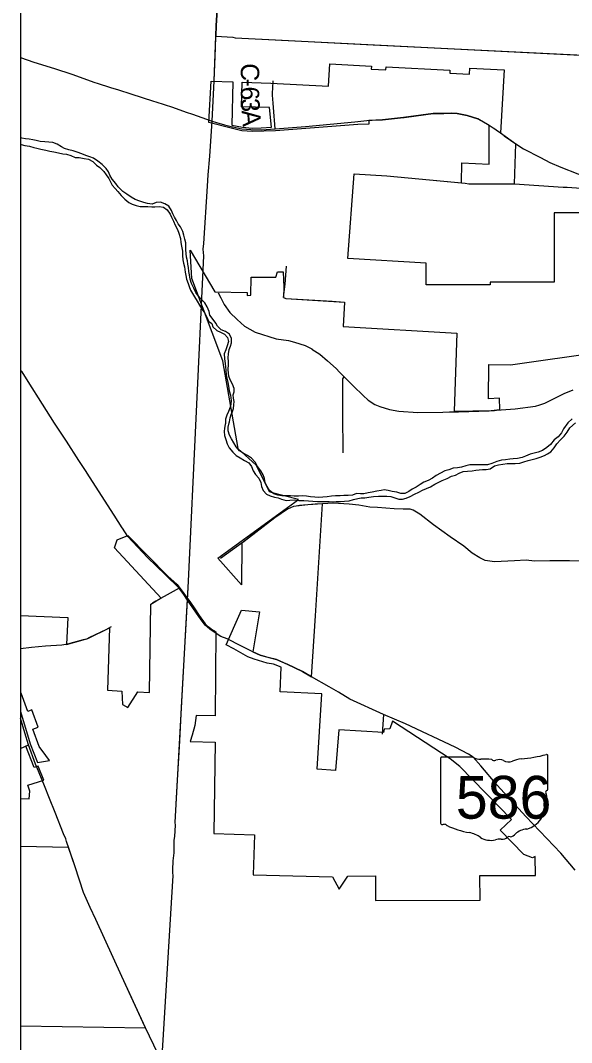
# Model space of a CAD drawing. Extents: x 41.3 to 81.6, y -19.3 to 2.7.
# Drawn here: x 43.265 to 44.697, y -1.388 to 1.27 of the extents above; entities that cross this region are included whole.
import ezdxf

# ---------------------------------------------------------------- set-up
doc = ezdxf.new("R2010")
doc.units = 0
for name, color, linetype in [('GM_X_Corporation', 7, 'Continuous'), ('GM_X_County_Road', 7, 'Continuous'), ('GM_X_County_Road_Text', 7, 'Continuous'), ('GM_X_Major_River', 7, 'Continuous'), ('GM_X_State_Route', 7, 'Continuous'), ('GM_X_State_Shield', 7, 'Continuous'), ('GM_X_Township', 7, 'Continuous'), ('GM_X_Township_Road', 7, 'Continuous'), ('SH_Data', 7, 'Continuous')]:
    doc.layers.add(name, color=color, linetype=linetype)

msp = doc.modelspace()

# ---------------------------------------------------------------- linework, layer by layer
at = {"layer": 'GM_X_Corporation'}
for points in [[(43.2645, 1.7338), (43.2645, -0.2777), (43.388, -0.2832), (43.3842, -0.3531), (43.4276, -0.3413), (43.4396, -0.3373), (43.4959, -0.3095), (43.4906, -0.4723), (43.5279, -0.4742), (43.5298, -0.5092), (43.5433, -0.5172), (43.5697, -0.4762), (43.6001, -0.4777), (43.6031, -0.248), (43.6162, -0.2404), (43.6303, -0.2329), (43.5094, -0.1021), (43.5157, -0.081), (43.5434, -0.0695), (43.6476, -0.1753), (43.6715, -0.1968), (43.7065, -0.244), (43.7181, -0.2604), (43.7293, -0.2776), (43.745, -0.2996), (43.7501, -0.3044), (43.7552, -0.3082), (43.7641, -0.3147), (43.7687, -0.3177), (43.7709, -0.3191), (43.7725, -0.3204), (43.7704, -0.5385), (43.7214, -0.5381), (43.718, -0.5638), (43.711, -0.5892), (43.7057, -0.6058), (43.771, -0.6074), (43.7675, -0.8448), (43.8728, -0.8478), (43.8698, -0.9517), (44.0759, -0.9576), (44.0935, -0.989), (44.1152, -0.9554), (44.1872, -0.9551), (44.1874, -1.0191), (44.4594, -1.0182), (44.4592, -0.9542), (44.6032, -0.9536), (44.603, -0.9047), (44.5956, -0.9077), (44.5732, -0.8991), (44.5119, -0.8359), (44.5407, -0.8081), (44.4071, -0.6702), (44.3818, -0.6505), (44.2316, -0.5529), (44.2247, -0.5725), (44.2097, -0.5731), (44.2085, -0.5823), (44.0926, -0.5748), (44.0834, -0.6809), (44.0359, -0.6774), (44.0482, -0.4814), (43.9398, -0.4759), (43.9419, -0.4122), (43.922, -0.4044), (43.906, -0.4016), (43.8723, -0.3912), (43.8558, -0.3849), (43.8192, -0.3645), (43.7992, -0.3544), (43.8222, -0.3032), (43.8392, -0.2638), (43.8857, -0.2678), (43.869, -0.3726), (43.888, -0.3806), (43.9298, -0.3923), (43.9581, -0.4039), (43.9975, -0.4234), (44.0215, -0.4372), (44.0319, -0.2787), (44.0497, 0.013), (44.0112, 0.0102), (43.9816, 0.0069), (43.9747, 0.0054), (43.9588, -0.001), (43.9262, -0.0238), (43.8399, -0.0897), (43.8394, -0.1983), (43.7777, -0.1291), (43.987, 0.0243), (43.9129, 0.0428), (43.877, 0.1133), (43.8294, 0.1562), (43.8304, 0.1564), (43.7903, 0.3842), (43.7099, 0.5986), (43.7057, 0.6719), (43.7702, 0.564), (43.8535, 0.562), (43.8535, 0.5546), (43.8635, 0.5549), (43.8643, 0.6021), (43.9288, 0.6024), (43.9331, 0.6157), (43.9479, 0.6157), (43.949, 0.5763), (43.9483, 0.5487), (43.9543, 0.5463), (44.1069, 0.5373), (44.1032, 0.4734), (44.3987, 0.4561), (44.3924, 0.2532), (44.4884, 0.2557), (44.5109, 0.2583), (44.5101, 0.2871), (44.4817, 0.2858), (44.4823, 0.3747), (44.5383, 0.3743), (44.776, 0.4078)], [(44.7163, 0.7696), (44.6523, 0.7696), (44.6522, 0.5888), (44.4858, 0.5888), (44.4858, 0.5824), (44.3194, 0.5824), (44.3194, 0.6384), (44.1154, 0.6508), (44.1318, 0.8708), (44.2173, 0.8653), (44.411, 0.8469), (44.4119, 0.899), (44.4834, 0.8957), (44.4834, 0.9967), (44.4536, 1.0133), (44.4261, 1.022), (44.4001, 1.0272), (44.3847, 1.0282), (44.3653, 1.0279), (44.3375, 1.0272), (44.2606, 1.0169), (44.206, 1.0115), (44.17, 1.0094), (44.1706, 0.9998), (44.1416, 0.9993), (44.0067, 0.9889), (43.9275, 0.9827), (43.8674, 0.9805), (43.84, 0.9827), (43.8127, 0.9892), (43.7539, 1.0039), (43.7607, 1.1118), (43.8165, 1.1097), (43.8138, 0.9976), (43.8419, 0.9919), (43.8673, 0.9891), (43.8906, 0.9901), (43.9171, 0.9924), (43.9124, 1.0433), (43.8389, 1.0452), (43.8405, 1.1088), (43.9152, 1.1061), (44.0654, 1.0989), (44.0684, 1.1565), (44.1771, 1.1508), (44.1767, 1.1428), (44.2146, 1.1408), (44.215, 1.1488), (44.3812, 1.1401), (44.3808, 1.1321), (44.4319, 1.1294), (44.4327, 1.1454), (44.5222, 1.1407), (44.5127, 0.9774), (44.5526, 0.9487), (44.5719, 0.9359), (44.6162, 0.9128), (44.6411, 0.9001), (44.6697, 0.8884), (44.7134, 0.8708)]]:
    msp.add_lwpolyline(points, dxfattribs=at)
for points in [[(43.2645, -0.5274), (43.2902, -0.6115), (43.3085, -0.6602), (43.3403, -0.6548), (43.3307, -0.6416), (43.3133, -0.6186), (43.2969, -0.5735), (43.3103, -0.5684), (43.2939, -0.5232), (43.2834, -0.5273), (43.2661, -0.4796), (43.2645, -0.4796)], [(43.2645, -0.754), (43.2871, -0.7543), (43.2887, -0.7341), (43.2833, -0.719), (43.3249, -0.7058), (43.3105, -0.6692), (43.3004, -0.6728), (43.2789, -0.6172), (43.2856, -0.6142), (43.2758, -0.5829), (43.2645, -0.5447)], [(43.2645, -1.3443), (43.5893, -1.35), (43.5279, -1.216), (43.4607, -1.0686), (43.4455, -1.0374), (43.4282, -0.9981), (43.4069, -0.9312), (43.3895, -0.8808), (43.2645, -0.8786)]]:
    msp.add_lwpolyline(points, close=True, dxfattribs=at)
at = {"layer": 'GM_X_County_Road'}
for points in [[(43.9212, 1.0541), (43.9212, 1.0547), (43.9194, 1.0753), (43.9204, 1.0995), (43.9213, 1.1064), (43.9214, 1.1126)], [(43.9264, 0.9873), (43.9221, 1.043), (43.9212, 1.0541)]]:
    msp.add_lwpolyline(points, dxfattribs=at)
at = {"layer": 'GM_X_Major_River'}
for points in [[(43.3491, 0.9521), (43.3385, 0.9534), (43.3276, 0.9537), (43.316, 0.9547), (43.3051, 0.9573), (43.2971, 0.9589), (43.2868, 0.9605), (43.2778, 0.9621), (43.2682, 0.9634), (43.2645, 0.964)], [(43.2645, 0.9472), (43.2665, 0.9467), (43.2762, 0.9445), (43.288, 0.9422), (43.2993, 0.939)], [(43.2993, 0.939), (43.3073, 0.937), (43.3179, 0.9345), (43.3301, 0.9325), (43.3407, 0.9299), (43.3516, 0.9277), (43.3635, 0.9254), (43.3747, 0.9231), (43.3846, 0.9215), (43.3956, 0.9186), (43.4065, 0.9135), (43.4174, 0.9128), (43.4299, 0.9108), (43.4414, 0.9086), (43.4524, 0.9028), (43.4626, 0.8935), (43.4709, 0.8873), (43.4815, 0.8764), (43.4876, 0.8684), (43.4943, 0.8584), (43.4982, 0.8501), (43.5033, 0.8414), (43.5106, 0.8327), (43.5177, 0.8243), (43.5263, 0.8144), (43.5363, 0.8044), (43.5465, 0.7964), (43.5549, 0.7915), (43.5651, 0.7883), (43.576, 0.7857), (43.596, 0.7857), (43.6062, 0.7847), (43.6143, 0.7847), (43.6249, 0.7853), (43.6361, 0.7837), (43.646, 0.7773), (43.6534, 0.766), (43.6575, 0.7577), (43.662, 0.748), (43.6665, 0.7371), (43.6729, 0.7262), (43.6764, 0.7165), (43.6809, 0.7024), (43.6815, 0.6918), (43.6831, 0.6828), (43.6856, 0.6697), (43.6862, 0.6581), (43.6865, 0.6472), (43.6888, 0.6385), (43.6913, 0.6289), (43.6926, 0.6151), (43.6942, 0.6067), (43.6961, 0.5968), (43.7002, 0.5858), (43.7031, 0.5778), (43.7069, 0.5682), (43.7117, 0.5592), (43.7168, 0.5505), (43.7242, 0.5396), (43.7296, 0.5293), (43.7364, 0.5187), (43.7441, 0.5084), (43.7495, 0.4965), (43.7533, 0.4874), (43.7617, 0.4811), (43.7648, 0.4727), (43.7748, 0.4631), (43.785, 0.4589), (43.7953, 0.4537), (43.803, 0.4454), (43.8052, 0.4345), (43.8017, 0.4236), (43.7981, 0.4133), (43.7942, 0.4027), (43.7949, 0.3892), (43.7964, 0.3773), (43.7977, 0.369), (43.7983, 0.36), (43.7996, 0.3484), (43.8012, 0.3394), (43.8037, 0.3279), (43.8056, 0.3189), (43.8075, 0.3067), (43.8107, 0.2954), (43.812, 0.2813), (43.8113, 0.272), (43.8097, 0.264), (43.8058, 0.2527), (43.801, 0.2428), (43.7978, 0.2325), (43.7973, 0.2219)], [(43.8083, 0.2258), (43.8093, 0.2364), (43.8119, 0.2447), (43.8161, 0.2527), (43.818, 0.2608), (43.819, 0.2701), (43.8197, 0.2791), (43.8184, 0.2877), (43.8175, 0.2961), (43.8201, 0.3041), (43.8197, 0.3124), (43.8159, 0.3237), (43.8095, 0.3349), (43.8063, 0.3446), (43.8054, 0.3526), (43.8044, 0.3616), (43.8051, 0.3747), (43.8058, 0.3828), (43.8045, 0.3918), (43.8052, 0.4027), (43.8071, 0.4139), (43.8107, 0.4223), (43.8136, 0.4316), (43.8133, 0.4428), (43.8078, 0.4534), (43.7976, 0.4608), (43.7867, 0.4647), (43.7767, 0.4746), (43.7723, 0.4827), (43.763, 0.4952), (43.7572, 0.5032), (43.755, 0.5126), (43.7499, 0.5248), (43.7435, 0.535), (43.7339, 0.545), (43.7278, 0.553), (43.7207, 0.5624), (43.715, 0.573), (43.7089, 0.5855), (43.7057, 0.5964), (43.7038, 0.6083), (43.7025, 0.6163), (43.7013, 0.6269), (43.6997, 0.6359), (43.6984, 0.6446), (43.6965, 0.6542), (43.6956, 0.6632), (43.6943, 0.6729), (43.6946, 0.6809), (43.6943, 0.6912), (43.6921, 0.7011), (43.6892, 0.7114), (43.6867, 0.7204), (43.6803, 0.7326), (43.6745, 0.7409), (43.6701, 0.7496), (43.6653, 0.758), (43.6608, 0.7666), (43.6573, 0.7756), (43.6499, 0.7866), (43.6403, 0.7927), (43.6287, 0.7966), (43.6175, 0.7959), (43.6066, 0.7921), (43.5944, 0.7934), (43.5854, 0.796), (43.5745, 0.7995), (43.5626, 0.804), (43.552, 0.8102), (43.5411, 0.8179), (43.5309, 0.825), (43.5187, 0.8365), (43.5126, 0.8459), (43.5027, 0.8565), (43.4969, 0.8674), (43.4931, 0.8758), (43.487, 0.8848), (43.4767, 0.895), (43.4658, 0.904), (43.4546, 0.9111), (43.4447, 0.915), (43.4344, 0.9185), (43.4238, 0.9231), (43.4123, 0.9269), (43.4014, 0.9305), (43.3904, 0.9334), (43.3792, 0.9363), (43.3712, 0.9408), (43.3596, 0.9482), (43.3491, 0.9521)], [(43.7973, 0.2219), (43.7966, 0.2191), (43.7947, 0.2095), (43.7944, 0.2009), (43.7953, 0.1903), (43.7982, 0.1797), (43.802, 0.1688), (43.8074, 0.1585), (43.8164, 0.1473), (43.8253, 0.138), (43.8355, 0.1318), (43.847, 0.1251), (43.8579, 0.119), (43.8652, 0.1094), (43.8694, 0.0988), (43.8754, 0.0885), (43.8844, 0.0792), (43.8898, 0.0679), (43.8914, 0.0574), (43.8955, 0.0474), (43.9045, 0.0381), (43.9141, 0.033), (43.9246, 0.0297), (43.9349, 0.0281), (43.9435, 0.0246), (43.955, 0.0217), (43.9652, 0.022), (43.9767, 0.0226), (43.9886, 0.0216), (44.0014, 0.0213), (44.0135, 0.0206), (44.0244, 0.0193), (44.0365, 0.0184), (44.0669, 0.0183), (44.0752, 0.018), (44.0855, 0.0186), (44.0966, 0.0183), (44.1069, 0.0192), (44.1187, 0.0208), (44.1305, 0.0237), (44.1414, 0.0269), (44.1501, 0.0278), (44.16, 0.0284), (44.1705, 0.0297), (44.1827, 0.0319), (44.1955, 0.0329), (44.2076, 0.0322), (44.2172, 0.0325), (44.2278, 0.0316), (44.238, 0.0283), (44.2482, 0.0248), (44.2581, 0.0245), (44.2671, 0.0273), (44.278, 0.0315), (44.2889, 0.0376), (44.3001, 0.0427), (44.3093, 0.0478), (44.3205, 0.0523), (44.3308, 0.0571), (44.3417, 0.0641), (44.3519, 0.0689), (44.3608, 0.0731), (44.3736, 0.0788), (44.3848, 0.0846), (44.3954, 0.0874), (44.4053, 0.0922), (44.4156, 0.0964), (44.4268, 0.0977), (44.4392, 0.098), (44.4485, 0.0999), (44.4568, 0.1008), (44.4655, 0.1018), (44.475, 0.1018), (44.4856, 0.104), (44.4965, 0.111), (44.5074, 0.1139), (44.5189, 0.1155), (44.5297, 0.1174), (44.54, 0.1177), (44.5509, 0.1177), (44.5627, 0.1183), (44.5736, 0.1218), (44.5844, 0.125), (44.595, 0.1279), (44.6049, 0.1304), (44.6158, 0.1336), (44.6267, 0.1381), (44.635, 0.1423), (44.643, 0.148), (44.6516, 0.1586), (44.6593, 0.1688), (44.6689, 0.1788), (44.6782, 0.1887), (44.6859, 0.1989), (44.6929, 0.2105), (44.7075, 0.2232)], [(44.6876, 0.2235), (44.6763, 0.2079), (44.6712, 0.197), (44.6625, 0.1871), (44.652, 0.1788), (44.6427, 0.1673), (44.6331, 0.1589), (44.6216, 0.1516), (44.6107, 0.1468), (44.6004, 0.1442), (44.5899, 0.1414), (44.5771, 0.1369), (44.5688, 0.133), (44.5563, 0.1302), (44.5451, 0.1292), (44.5365, 0.1286), (44.5259, 0.127), (44.5154, 0.1261), (44.5029, 0.1226), (44.4898, 0.1178), (44.4786, 0.1143), (44.4664, 0.114), (44.4556, 0.1143), (44.4447, 0.114), (44.4328, 0.1143), (44.422, 0.1111), (44.4114, 0.1079), (44.4005, 0.1063), (44.3893, 0.1051), (44.3778, 0.1006), (44.3679, 0.0984), (44.3567, 0.092), (44.3455, 0.0862), (44.3356, 0.0795), (44.3244, 0.0734), (44.3132, 0.069), (44.3039, 0.0632), (44.2934, 0.0558), (44.2825, 0.0504), (44.2742, 0.045), (44.2639, 0.0395), (44.2534, 0.0395), (44.2428, 0.0431), (44.231, 0.0447), (44.2208, 0.0476), (44.2102, 0.0489), (44.2019, 0.0476), (44.1907, 0.0457), (44.1792, 0.0428), (44.1683, 0.0409), (44.1571, 0.0387), (44.1488, 0.0384), (44.1382, 0.0394), (44.1274, 0.0352), (44.1162, 0.0343), (44.1056, 0.034), (44.0954, 0.033), (44.0836, 0.0337), (44.0733, 0.0327), (44.0621, 0.0311), (44.0503, 0.0296), (44.0401, 0.0293), (44.0298, 0.0302), (44.0183, 0.0309), (44.0084, 0.0328), (43.9982, 0.0338), (43.9873, 0.0329), (43.9758, 0.0326), (43.9665, 0.0332), (43.9547, 0.0335), (43.9438, 0.0336), (43.9336, 0.0355), (43.9234, 0.039), (43.9122, 0.0474), (43.9055, 0.058), (43.901, 0.0683), (43.8991, 0.0782), (43.8959, 0.0881), (43.8895, 0.0984), (43.8812, 0.1097), (43.8745, 0.1206), (43.8653, 0.1312), (43.8544, 0.1382), (43.8439, 0.1443), (43.8336, 0.1508), (43.825, 0.161), (43.8193, 0.1713), (43.8135, 0.1813), (43.8084, 0.1915), (43.8046, 0.2021), (43.8044, 0.2119), (43.8073, 0.2234), (43.8083, 0.2258)], [(44.6986, 0.2338), (44.6876, 0.2235)]]:
    msp.add_lwpolyline(points, dxfattribs=at)
at = {"layer": 'GM_X_State_Route'}
msp.add_line((43.2645, -0.6238), (43.2856, -0.6142), dxfattribs=at)
for points in [[(43.2645, 1.1729), (43.2993, 1.1614), (43.3532, 1.1448), (43.3977, 1.13), (43.4576, 1.1084), (43.4639, 1.1065), (43.4989, 1.0952), (43.5196, 1.0889), (43.5512, 1.079), (43.6102, 1.06), (43.6164, 1.0579), (43.6597, 1.0439), (43.6952, 1.0309), (43.7116, 1.0254), (43.7599, 1.0088)], [(44.1785, 1.0099), (44.206, 1.0115), (44.2606, 1.0169), (44.2625, 1.0171)], [(44.2625, 1.0171), (44.3375, 1.0272), (44.3631, 1.0279)], [(44.3631, 1.0279), (44.3653, 1.0279), (44.3847, 1.0282), (44.4001, 1.0272), (44.4261, 1.022), (44.4536, 1.0133), (44.4801, 0.9989), (44.4933, 0.9899), (44.4974, 0.9873)], [(43.7599, 1.0088), (43.7632, 1.0076), (43.7741, 1.0045), (43.7947, 0.9981), (43.816, 0.9927), (43.8169, 0.9925)], [(43.8169, 0.9925), (43.8401, 0.9873), (43.8632, 0.9858), (43.8916, 0.9855), (43.9264, 0.9873)], [(43.9264, 0.9873), (43.9264, 0.9873), (44.0059, 0.9935), (44.1336, 1.006), (44.1654, 1.0091), (44.1785, 1.0099)], [(44.4974, 0.9873), (44.5045, 0.9828)], [(44.5045, 0.9828), (44.5145, 0.9764), (44.5223, 0.9693), (44.5526, 0.9487), (44.5719, 0.9359), (44.6162, 0.9128), (44.6411, 0.9001), (44.6697, 0.8884), (44.7134, 0.8708), (44.7405, 0.8618)], [(43.4268, 0.1097), (43.4162, 0.1252), (43.384, 0.1759), (43.3527, 0.2227), (43.3215, 0.272), (43.2846, 0.3307), (43.2689, 0.3555), (43.2645, 0.3602)], [(43.4442, 0.0831), (43.4336, 0.0997), (43.4268, 0.1097)], [(43.5297, -0.0511), (43.5292, -0.0502), (43.508, -0.0168), (43.4442, 0.0831)], [(43.6768, -0.2068), (43.6416, -0.172), (43.5952, -0.1267), (43.5438, -0.0727), (43.5297, -0.0511)], [(43.8021, -0.3386), (43.7858, -0.3324), (43.7731, -0.3246), (43.7565, -0.3135), (43.7447, -0.3029), (43.7339, -0.2889), (43.7205, -0.2689), (43.699, -0.2376), (43.6893, -0.2234), (43.6768, -0.2068)], [(43.9496, -0.4004), (43.9298, -0.3923), (43.9089, -0.3867), (43.9026, -0.3849), (43.888, -0.3806), (43.869, -0.3726), (43.8339, -0.3547), (43.8057, -0.34), (43.8021, -0.3386)], [(44.7068, -0.9396), (44.6692, -0.8956), (44.5784, -0.8008), (44.5037, -0.7185), (44.4615, -0.6683), (44.4412, -0.6461), (44.4291, -0.6383), (44.395, -0.6202), (44.2655, -0.5593), (44.2085, -0.5351), (44.1204, -0.4949), (44.0914, -0.4774), (44.0672, -0.4635), (44.0214, -0.4371), (43.9975, -0.4234), (43.9581, -0.4039), (43.9496, -0.4004)], [(43.2856, -0.6142), (43.2758, -0.5829), (43.2645, -0.5447)], [(43.3068, -0.6723), (43.3034, -0.6642), (43.2856, -0.6142)], [(43.3269, -0.721), (43.3068, -0.6723)], [(43.3844, -0.8652), (43.3821, -0.8582), (43.3766, -0.8456), (43.3549, -0.7896), (43.3404, -0.7534), (43.3269, -0.721)], [(43.5522, -1.269), (43.5279, -1.216), (43.4607, -1.0686), (43.4455, -1.0374), (43.4282, -0.9981), (43.4069, -0.9312), (43.3909, -0.8853), (43.3844, -0.8652)], [(43.5877, -1.3463), (43.5522, -1.269)], [(43.6215, -1.4164), (43.5893, -1.35), (43.5877, -1.3463)]]:
    msp.add_lwpolyline(points, dxfattribs=at)
at = {"layer": 'GM_X_State_Shield'}
for p, q in [((44.3569, -0.649), (44.3569, -0.8181)), ((44.4412, -0.6461), (44.3596, -0.6461)), ((44.6353, -0.7303), (44.6353, -0.6419)), ((44.6353, -0.7303), (44.6353, -0.7303))]:
    msp.add_line(p, q, dxfattribs=at)
for centre, major_axis, start_param, end_param in [((44.3601, -0.6486), (0.00323, 0), 1.712693, 3.28349), ((44.4606, -0.6265), (0.0313, 0), 4.042523, 4.731795), ((44.471, -0.741), (0.1123, 0), 1.404758, 1.657858), ((44.4965, -0.6478), (0.00903, 0), 3.836095, 5.185415), ((44.5097, -0.6673), (0.0188, 0), 0.950623, 2.079405), ((44.5339, -0.6405), (0.0226, 0), 4.081561, 5.145723), ((44.5738, -0.6977), (0.0594, 0), 1.699011, 2.107814), ((44.5361, -0.4156), (0.2953, 0), 4.814394, 5.042369), ((44.6322, -0.6415), (0.0031, 0), 6.141152, 7.989035), ((44.6346, -0.7368), (0.0048, 0), 1.883978, 3.671073), ((44.6041, -0.748), (0.0288, 0), 5.934695, 6.695948), ((44.632, -0.7307), (0.00332, 0), 5.05454, 6.418171), ((44.5527, -0.7786), (0.0739, 0), 5.101752, 6.440018), ((44.6464, -0.7673), (0.021, 0), 2.387724, 3.262537), ((44.3601, -0.8184), (0.00325, 0), 3.00124, 4.508301), ((44.3606, -0.8011), (0.0248, 0), 4.665946, 4.897461), ((44.3657, -0.8278), (0.00895, 0), 0.519207, 1.627899), ((44.4787, -0.6759), (0.2132, 0), 4.195997, 4.488961), ((44.4152, -0.894), (0.0667, 0), 0.823519, 1.323587), ((44.5326, -0.8344), (0.0239, 0), 4.937069, 5.64225), ((44.5838, -0.8655), (0.0404, 0), 1.647645, 2.488434), ((44.4873, -0.8286), (0.0423, 0), 4.026481, 4.996735), ((44.5118, -0.8871), (0.0348, 0), 1.495662, 1.94098), ((44.5149, -0.8413), (0.0226, 0), 4.691044, 5.507374), ((44.5353, -0.8577), (0.00635, 0), 1.147584, 2.315152)]:
    msp.add_ellipse(centre, major_axis=major_axis, ratio=0.8, start_param=start_param, end_param=end_param, dxfattribs=at)
at = {"layer": 'GM_X_Township'}
for points in [[(43.2645, 1.7338), (43.2645, -1.9721)], [(48.1343, 1.7338), (43.8015, 1.7338), (43.7893, 1.525), (43.7809, 1.3914), (43.7796, 1.3646), (43.7767, 1.3102), (43.7737, 1.256), (43.7724, 1.2283), (43.8167, 1.2263), (43.8231, 1.2245), (45.083, 1.1614)], [(43.6324, -1.4381), (43.6611, -0.9536), (43.6606, -0.947), (43.6608, -0.939), (43.6619, -0.9156), (43.6639, -0.8952), (43.6644, -0.8621), (43.6659, -0.852), (43.6672, -0.8226), (43.6667, -0.8164), (43.7018, -0.1885), (43.7411, 0.6576), (43.7398, 0.6748), (43.7414, 0.6898), (43.7508, 0.8382), (43.7527, 0.868), (43.7569, 0.9165), (43.7632, 1.0076), (43.7677, 1.1123), (43.7724, 1.2283), (43.7737, 1.256), (43.7767, 1.3102)], [(43.6324, -1.4381), (43.6611, -0.9536), (43.6606, -0.947), (43.6608, -0.939), (43.6619, -0.9156), (43.6639, -0.8952), (43.6644, -0.8621), (43.6659, -0.852), (43.6672, -0.8226), (43.6667, -0.8164), (43.672, -0.7209), (43.6786, -0.6036), (43.6835, -0.5162), (43.699, -0.2376), (43.7018, -0.1885), (43.7411, 0.6576), (43.7398, 0.6748), (43.7414, 0.6898), (43.7508, 0.8382), (43.7527, 0.868), (43.7569, 0.9165), (43.7632, 1.0076), (43.7677, 1.1123), (43.7712, 1.1982), (43.7724, 1.2283), (43.8167, 1.2263), (43.8231, 1.2245), (43.928, 1.2192), (44.1816, 1.2065), (44.7642, 1.1774)]]:
    msp.add_lwpolyline(points, dxfattribs=at)
at = {"layer": 'GM_X_Township_Road'}
for points in [[(44.5488, 0.8444), (44.5526, 0.9487)], [(44.1318, 0.8708), (44.2173, 0.8653), (44.4204, 0.846)], [(44.6855, 0.8356), (44.698, 0.8355), (44.7222, 0.8337), (44.7407, 0.8336), (44.7484, 0.835), (44.7533, 0.8378), (44.7594, 0.8432), (44.7634, 0.8542)], [(44.4204, 0.846), (44.4301, 0.845), (44.5488, 0.8444), (44.6755, 0.8358), (44.6775, 0.8357)], [(44.6775, 0.8357), (44.6855, 0.8356)], [(43.9483, 0.5487), (43.9524, 0.5841), (43.9565, 0.6303)], [(43.7788, 0.5614), (43.7858, 0.5482), (43.7944, 0.5312), (43.8089, 0.5103), (43.8282, 0.4922), (43.8472, 0.4748), (43.8751, 0.4587), (43.9293, 0.4416), (43.9616, 0.4371), (43.9774, 0.4326), (44.005, 0.4245), (44.0216, 0.4154), (44.0223, 0.4149)], [(43.9483, 0.5487), (43.9543, 0.5463), (44.0751, 0.5392)], [(44.0751, 0.5392), (44.0751, 0.5392), (44.1069, 0.5373)], [(44.0223, 0.4149), (44.0425, 0.4017), (44.0626, 0.3846), (44.0857, 0.3644), (44.0942, 0.3552)], [(44.0942, 0.3552), (44.1058, 0.3427), (44.1302, 0.3186), (44.1551, 0.2942), (44.1686, 0.2824), (44.1862, 0.2706), (44.1989, 0.2655), (44.2239, 0.2575), (44.2478, 0.2534), (44.2974, 0.2502), (44.3622, 0.2511), (44.38, 0.2514), (44.3853, 0.2515)], [(44.1039, 0.1448), (44.1023, 0.2475), (44.1026, 0.3379), (44.1058, 0.3427)], [(44.5025, 0.2559), (44.5504, 0.2593), (44.6032, 0.2669), (44.6148, 0.2698), (44.628, 0.2743), (44.6676, 0.2945), (44.678, 0.2997), (44.7013, 0.309)], [(44.3853, 0.2515), (44.4029, 0.2517), (44.4827, 0.2545), (44.4969, 0.2555), (44.5025, 0.2559)], [(43.9898, 0.0079), (43.9816, 0.0069), (43.9747, 0.0054), (43.9588, -0.001), (43.9262, -0.0238), (43.846, -0.0852), (43.8399, -0.0897), (43.8318, -0.0956)], [(44.031, 0.0119), (44.0304, 0.0119), (44.0112, 0.0102), (44.0007, 0.0092), (43.9898, 0.0079)], [(44.7366, -0.1365), (44.692, -0.1355), (44.6408, -0.1352), (44.6012, -0.1368), (44.5796, -0.1343), (44.5487, -0.1352), (44.4969, -0.138), (44.4725, -0.1348), (44.4585, -0.1276), (44.439, -0.1159), (44.417, -0.0974), (44.3819, -0.0728), (44.3384, -0.0422), (44.303, -0.0139), (44.2943, -0.0088), (44.2853, -0.0039), (44.2779, -0.001), (44.2594, -0.0012), (44.2357, -0.0006), (44.193, 0.0027), (44.1726, 0.0043), (44.1446, 0.0092), (44.1194, 0.0116), (44.0773, 0.0147), (44.0497, 0.013), (44.031, 0.0119)], [(43.8318, -0.0956), (43.785, -0.1299)], [(43.6768, -0.2068), (43.6385, -0.2286)], [(43.6385, -0.2286), (43.6368, -0.2296), (43.6162, -0.2404), (43.6076, -0.2454)], [(43.5006, -0.3069), (43.4866, -0.3147), (43.4444, -0.3353), (43.4358, -0.3391), (43.4276, -0.3413), (43.3866, -0.3525)], [(43.3866, -0.3525), (43.3855, -0.3527), (43.3842, -0.3531), (43.3828, -0.3535), (43.3724, -0.3553), (43.3297, -0.3579), (43.2935, -0.361), (43.2645, -0.3642)], [(44.2085, -0.5351), (44.2046, -0.5864)]]:
    msp.add_lwpolyline(points, dxfattribs=at)
at = {"layer": 'SH_Data'}
msp.add_line((43.2645, 1.7338), (43.2645, -3.5953), dxfattribs=at)

# ---------------------------------------------------------------- texts
at = {"layer": 'GM_X_County_Road_Text'}
for s, rotation, p in [('C', 268.6377, (43.8379, 1.1588)), ('6', 271.4066, (43.8368, 1.0972)), ('-', 269.5633, (43.837, 1.1186)), ('3', 273.0064, (43.8376, 1.0662)), ('A', 274.7777, (43.8393, 1.035))]:
    msp.add_text(s, height=0.048, rotation=rotation, dxfattribs=at).set_placement(p)
at = {"layer": 'GM_X_State_Shield'}
msp.add_text('586', height=0.11138, dxfattribs=at).set_placement((44.3964, -0.8061))

doc.saveas('drawing.dxf')
